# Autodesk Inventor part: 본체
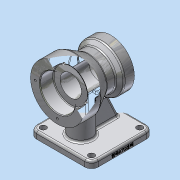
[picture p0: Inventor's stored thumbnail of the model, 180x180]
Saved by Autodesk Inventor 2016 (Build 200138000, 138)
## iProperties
Created: 2019-01
Part Number: 본체
Material: 알루미늄 6061
Document SubType Name: Modeling
Designer: Administrator
Density: 2.7 g/cm^3
Appearance: 알루미늄 - 평지
Mass: 898.816 g
Surface Area: 600.964 cm^2
Volume: 332.895 cm^3
Author: Administrator
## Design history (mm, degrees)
sketch "스케치1"
  geometry: L1 (-46, 46)-(46, 46); L2 (46, 46)-(46, -46); L3 (46, -46)-(-46, -46); L4 (-46, -46)-(-46, 46); L5 (-46, 46)-(46, -46); L6 (46, 46)-(-46, -46); 1 further point
  constraints: 12 end point, 2 midpoint, 2 parallel, 1 horizontal, 1 perpendicular
  dimensions: "d0" = 92 distance of L2.end L3.end; "d1" = 92 distance of L1.end L2.end
extrude "돌출1" new body sketch "스케치1" distance "d2" = 10; taper "d3" = 0 deg
sketch "스케치2"
  geometry: L1 (-46, 46)-(-46, -46) reference; L2 (-46, -46)-(46, -46) reference; C1 r 16 at (0, -16); 1 further point
  constraints: 1 centre point
  dimensions: "d4" = 16 radius of C1; "d5" = 46 distance from line of L1 C1.centre; "d6" = 30 distance from line of C1.centre L2
extrude "돌출2" join sketch "스케치2" distance "d7" = 80; taper "d8" = 0 deg
sketch "스케치3"
  geometry: L1 (0, 0)-(-10, 0) reference; 2 further points
  constraints: 1 other
  dimensions: "d9" = 4 distance of point (0, 46) point (-4, 46); "d10" = 46 distance from line of L1 point (-4, 46)
feature "엠보싱1" sketch "스케치3" dims "d0" = 92, "d1" = 92, "d11" = 0.5, "d12" = 0
sketch "스케치4"
  geometry: L1 (-51, 80)-(29, 80); L2 (-51, 80)-(-51, 120); L3 (-51, 120)-(-26, 120); L4 (-5.215, 108)-(8.126, 108); L5 (8.126, 108)-(14, 115); L6 (14, 115)-(29, 115); L7 (29, 115)-(29, 80); L8 (-26, 120)-(-5.215, 108); L9 (-46, 0)-(-46, 10) reference; 1 further point
  constraints: 16 end point, 2 parallel, 2 perpendicular, 1 horizontal, 1 vertical
  dimensions: "d13" = 80 distance from line of point (0, 0) L1; "d14" = 80 distance of L1.start L1.end; "d15" = 80 diameter of L3 L1; "d16" = 25 distance of L2.end L3.end; "d17" = 56 diameter of L4 L1; "d18" = 15 distance of L5.end L6.end; "d19" = 70 diameter of L6 L1; "d20" = 50 deg angle of L4 L5; "d21" = 30 deg angle of L4 L8; "d22" = 5 distance between parallel lines of L9 L2
revolve "회전1" sketch "스케치4" stored, may be unused: angle "d23" = 90 deg
sketch "스케치5"
  geometry: L1 (23.767, 36.233)-(36, 10); L2 (46, 0)-(46, 10) reference; L3 (46, 10)-(-46, 10) reference; 1 further point
  constraints: 2 end point, 1 point on line
  dimensions: "d24" = 25 deg angle of L2 L1; "d25" = 10 distance from line of L2 L1.end
feature "리브1" sketch "스케치5" dims "d26" = 1, "d27" = 10, "d28" = 0, "d29" = 0, "d30" = 1, "d31" = 1
sketch "스케치6"
  geometry: L1 (-51, 80)-(29, 80); L2 (-51, 80)-(-51, 106); L3 (-51, 106)-(-31, 106); L4 (-31, 106)-(-31, 96); L5 (-31, 96)-(12, 96); L6 (12, 96)-(12, 100); L7 (12, 100)-(29, 100); L8 (29, 100)-(29, 80); L9 (29, 45)-(29, 115) reference; 1 further point
  constraints: 16 end point, 6 perpendicular, 1 horizontal, 1 midpoint, 1 vertical
  dimensions: "d32" = 80 distance from line of point (0, 0) L1; "d33" = 80 distance of L1.start L1.end; "d34" = 20 distance of L2.end L3.end; "d35" = 17 distance of L6.end L7.end; "d36" = 52 diameter of L3 L1; "d37" = 32 diameter of L5 L1; "d38" = 40 diameter of L7 L1
revolve "회전2" sketch "스케치6" stored, may be unused: angle "d39" = 90 deg
sketch "스케치7"
  geometry: C1 r 40 at (0, 0) reference; 2 further points
  constraints: 1 vertical alignment
  dimensions: "d40" = 33 distance of C1.centre point (0, 33)
hole "구멍1" sketch "스케치7" at (0, 33) diameter "d41" = 3.242; stored, may be unused: countersink angle "d45" = 90 deg, drill point angle "d47" = 118 deg; dims "d42" = 9, "d43" = 4, "d44" = 2, "d46" = 11
sketch "스케치8"
  geometry: C1 r 35 at (0, 0) reference; 2 further points
  constraints: 1 vertical alignment
  dimensions: "d51" = 27.5 distance of C1.centre point (0, -27.5)
hole "구멍2" sketch "스케치8" at (0, -27.5) diameter "d52" = 3.242; stored, may be unused: countersink angle "d56" = 90 deg, drill point angle "d58" = 118 deg; dims "d53" = 9, "d54" = 4, "d55" = 2, "d57" = 11
fillet "모깎기1" dims "d62" = 10
sketch "스케치9"
  geometry: A1 r 10 centre (-36, 36) between (-36, 46) and (-46, 36) reference; A2 r 10 centre (36, 36) between (46, 36) and (36, 46) reference; A3 r 10 centre (36, -36) between (36, -46) and (46, -36) reference; A4 r 10 centre (-36, -36) between (-46, -36) and (-36, -46) reference; 5 further points
  constraints: 4 coincident
hole "구멍3" sketch "스케치9" at (-36, 36), (36, 36), (36, -36), (-36, -36) diameter "d63" = 9; stored, may be unused: countersink angle "d67" = 90 deg, drill point angle "d69" = 118 deg; dims "d64" = 9, "d65" = 4, "d66" = 2, "d68" = 11
fillet "모깎기2" dims "d70" = 3
fillet "모깎기3" dims "d71" = 3
fillet "모깎기4" dims "d72" = 3
fillet "모깎기5" dims "d73" = 3
fillet "모깎기6" dims "d74" = 3
chamfer "모따기1" distance "d75" = 1; stored, may be unused: second distance "d76" = 2, angle "d77" = 45 deg
fillet "모깎기7" dims "d78" = 1, "d79" = 0.6
feature "분할1"
node "솔리드1"
pattern_circular "원형 패턴1" dims angle "d49" = 360 deg
pattern_circular "원형 패턴2" dims angle "d60" = 360 deg
